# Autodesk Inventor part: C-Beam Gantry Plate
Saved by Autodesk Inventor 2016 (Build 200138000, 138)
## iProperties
Created: 2015-11
Part Number: C-Beam Gantry Plate
Material: Generic
Document SubType Name: Modeling
Designer: John
Density: 1 g/cm^3
Appearance: Default
Author: John
Revision Number: ANY
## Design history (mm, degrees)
feature "Cut-Extrude1"
body "Solid1"
